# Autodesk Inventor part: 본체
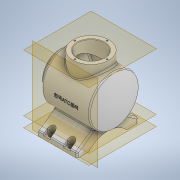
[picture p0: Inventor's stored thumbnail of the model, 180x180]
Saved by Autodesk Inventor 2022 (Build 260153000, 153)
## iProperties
Created: 2023-04
Part Number: 본체
Material: 일반
Document SubType Name: Modeling
Designer: Admin
Density: 1 g/cm^3
Appearance: 기본값
Author: Admin
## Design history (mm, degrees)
sketch "스케치1"
  geometry: L1 (-348.762, 0)-(521.266, 0) reference; L2 (0, -10.134)-(0, 60.805) reference; L3 (-224.472, 0)-(396.976, 0); L4 (-55.746, 0)-(-55.746, 36); L5 (-55.746, 36)-(-43.746, 36); L6 (-43.746, 36)-(-43.746, 50); L7 (-43.746, 50)-(52.59, 50); A1 r 113 centre (-48.746, 0) between (64.254, 0) and (52.59, 50); 1 further point
  constraints: 10 end point, 5 point on line, 3 perpendicular, 2 point on circle, 1 centre point, 1 vertical
  dimensions: "d3" = 72 diameter of L5 L3; "d4" = 50 distance between parallel lines of L1 L7; "d5" = 12 distance of L4.end L5.end; "d6" = 226 diameter of A1; "d7" = 48.74631 distance from line of L2 A1.centre; "d8" = 120 distance from line of A1.start L4
revolve "회전1" sketch "스케치1" stored, may be unused: angle "d9" = 360 deg
sketch "스케치2"
  geometry: L1 (-108.704, 0)-(76.451, 0) reference; L2 (0, -92.467)-(0, 110.746) reference; L3 (-34.165, -15.107)-(-67, -62); L4 (-67, -62)-(-77, -62); L5 (-77, -62)-(-77, 62); L6 (-77, 62)-(-67, 62); L7 (-67, 62)-(-34.165, 15.107); L8 (-34.165, 15.107)-(-34.165, -15.107); 1 further point
  constraints: 12 end point, 2 perpendicular, 1 horizontal, 1 parallel, 1 other
  dimensions: "d12" = 124 distance of L4.end L5.end; "d13" = 10 distance of L5.end L6.end; "d14" = 55 deg angle of L7 L6; "d15" = 55 deg angle of L3 L4; "d16" = 10 distance of L3.end L4.end; "d17" = 15.1066 distance from line of L1 L7.end; "d18" = 77 distance between parallel lines of L2 L5
extrude "돌출1" join sketch "스케치2" stored distance "d19" = 80; taper "d20" = 0 deg
node "작업 평면1"
sketch "스케치3"
  geometry: L1 (55.746, 36)-(55.746, -36) reference; L2 (79.746, 0)-(-88.254, 0) reference; L3 (0, -86.8)-(0, 86.8) reference; C1 r 36 at (-6.254, 0); C2 r 27 at (-6.254, 0); 1 further point
  constraints: 2 centre point, 1 coincident, 1 point on line
  dimensions: "d22" = 72 diameter of C1; "d23" = 62 distance from line of C1.centre L1; "d24" = 54 diameter of C2
extrude "돌출2" join sketch "스케치3" stored distance "d25" = 40; taper "d26" = 0 deg
sketch "스케치4"
  geometry: L1 (-92.77, 0)-(99.642, 0); L2 (0, -105.4)-(0, 93.4) reference; L3 (-55.746, -36)-(-55.746, 36) reference; L4 (-55.746, 27)-(-36.746, 27); L5 (-36.746, 27)-(-36.746, 40); L6 (57.254, 40.2)-(57.254, 39.154); L7 (64.254, 0)-(64.254, 54.671); L8 (-33.746, 43)-(46.723, 43); L9 (56.861, 40.2)-(57.254, 40.2); L10 (-55.746, 27)-(-55.746, 0); L11 (-116.841, 0)-(170.726, 0); A1 r 113 centre (-48.746, 0) between (52.59, -50) and (52.59, 50) reference; A2 r 113 centre (-55.746, 0) between (57.254, 0) and (49.518, 41.091); A3 r 3 centre (-33.746, 40) between (-33.746, 43) and (-36.746, 40); A4 r 3 centre (46.723, 40) between (49.518, 41.091) and (46.723, 43); 6 further points
  constraints: 18 end point, 10 point on circle, 6 tangent, 4 perpendicular, 3 centre point, 3 point on line, 2 horizontal, 1 equal radius, 1 vertical, 6 other
  dimensions: "d27" = 7 distance between parallel lines of L6 L7; "d28" = 226 diameter of A2; "d29" = 27 distance of the line from the sketch origin of L4; "d30" = 43 distance of the line from the sketch origin of L8; "d31" = 19 distance of L4.start L4.end; "d32" = 3 radius of A3
revolve "회전2" sketch "스케치4" stored, may be unused: angle "d33" = 360 deg
sketch "스케치5"
  geometry: L1 (-64.144, -60)-(74.974, -60); L2 (-62, -77)-(62, -77) reference; L3 (-91.968, 0)-(102.797, 0) reference; L4 (0, -210.029)-(0, 110.838) reference; A1 r 52.096 centre (0, -112.096) between (-38.5, -77) and (38.5, -77); 1 further point
  constraints: 3 point on line, 2 end point, 2 point on circle, 1 centre point, 1 horizontal, 1 tangent
  dimensions: "d34" = 17 distance between parallel lines of L2 L1; "d35" = 77 distance of A1.start A1.end
extrude "돌출3" cut sketch "스케치5" distance "d36" = 100; taper "d37" = 0 deg
sketch "스케치6"
  geometry: C1 r 36 at (-6.254, 0) reference; C2 r 27 at (-6.254, 0); 1 further point
  constraints: 1 centre point, 1 coincident
  dimensions: "d38" = 54 diameter of C2
extrude "돌출4" cut sketch "스케치6" distance "d39" = 40; taper "d40" = 0 deg
sketch "스케치7"
  geometry: L1 (-86, 0)-(82, 0) reference; L2 (-6.254, 86.8)-(-6.254, -86.8) reference; C1 r 27 at (0, 0) reference; A1 r 32.5 centre (0, 0) between (32.5, 0) and (0, 32.5); 3 further points
  constraints: 4 point on circle, 3 point on line, 1 centre point, 1 coincident
  dimensions: "d41" = 65 diameter of A1; "d42" = 32.5 distance from line of L1 point (0, -32.5); "d43" = 32.5 distance from line of L1 A1.end
hole "구멍1" sketch "스케치7" at (32.5, 0), (0, 32.5), (-32.5, 0), (0, -32.5) diameter "d44" = 3.242; stored, may be unused: countersink angle "d48" = 90 deg, drill point angle "d50" = 118 deg; dims "d45" = 8, "d46" = 4, "d47" = 2, "d49" = 10
sketch "스케치8"
  geometry: L1 (0, -105.4)-(0, 93.4) reference; L2 (-86.8, 0)-(86.8, 0) reference; A1 r 32.5 centre (0, 0) between (0, 32.5) and (-32.5, 0); 3 further points
  constraints: 4 point on circle, 4 point on line, 1 centre point, 1 coincident
  dimensions: "d51" = 65 diameter of A1
hole "구멍2" sketch "스케치8" at (0, 32.5), (-32.5, 0), (0, -32.5), (32.5, 0) diameter "d52" = 3.242; stored, may be unused: countersink angle "d56" = 90 deg, drill point angle "d58" = 118 deg; dims "d53" = 8, "d54" = 4, "d55" = 2, "d57" = 10
node "작업 평면2"
sketch "스케치9"
  geometry: L1 (-55.746, -36)-(-55.746, 36) reference; L2 (-79.746, 0)-(88.254, 0) reference; 2 further points
  constraints: 1 point on line, 1 other
  dimensions: "d60" = 62 distance from line of L1 point (6.254, 0)
feature "엠보싱1" sketch "스케치9" dims "d3" = 72, "d4" = 50, "d5" = 12, "d6" = 226, "d7" = 48.74631, "d8" = 120, "d61" = 0.5, "d62" = 0
node "작업 평면3"
sketch "스케치11"
  geometry: L1 (0, 124)-(80, 124) reference; L2 (0, 0)-(80, 0) reference; L3 (0, 100.5)-(0, 124) reference; L4 (0, 0)-(0, 23.5) reference; 5 further points
  dimensions: "d72" = 8 distance from line of L1 point (20, 116); "d73" = 8 distance from line of L1 point (60, 116); "d74" = 8 distance from line of L2 point (20, 8); "d75" = 8 distance from line of L2 point (60, 8); "d76" = 40 distance of point (60, 116) point (20, 116); "d77" = 40 distance of point (60, 8) point (20, 8); "d78" = 20 distance from line of L3 point (20, 116); "d79" = 20 distance from line of L4 point (20, 8)
hole "구멍3" sketch "스케치11" at (20, 116), (60, 116), (20, 8), (60, 8) diameter "d80" = 9; stored, may be unused: countersink angle "d84" = 90 deg, drill point angle "d86" = 0 deg; dims "d81" = 8, "d82" = 4, "d83" = 2, "d85" = 6
node "작업 평면4"
sketch "스케치12"
  geometry: L1 (-27, 54)-(-27, 62); L2 (40, 62)-(-40, 62) reference; L3 (-13, 54)-(-13, 62); L4 (-13, 62)-(-27, 62); L5 (13, 54)-(13, 62); L6 (13, 62)-(27, 62); L7 (27, 62)-(27, 54); L8 (-27, -54)-(-27, -62); L9 (40, -62)-(-40, -62) reference; L10 (-13, -54)-(-13, -62); L11 (-13, -62)-(-27, -62); L12 (13, -54)-(13, -62); L13 (27, -62)-(27, -54); L14 (27, -62)-(13, -62); C1 r 4.5 at (-20, 54) reference; C2 r 4.5 at (20, 54) reference; C3 r 4.5 at (-20, -54) reference; C4 r 4.5 at (20, -54) reference; A1 r 7 centre (-20, 54) between (-27, 54) and (-13, 54); A2 r 7 centre (20, 54) between (13, 54) and (27, 54); A3 r 7 centre (-20, -54) between (-27, -54) and (-13, -54); A4 r 7 centre (20, -54) between (13, -54) and (27, -54); 7 further points
  constraints: 24 end point, 14 point on line, 8 point on circle, 4 centre point, 4 coincident, 4 perpendicular, 4 tangent, 2 vertical
  dimensions: "d88" = 14 diameter of A1; "d89" = 14 diameter of A2; "d90" = 14 diameter of A3; "d91" = 14 diameter of A4
extrude "돌출5" cut sketch "스케치12" distance "d92" = 21; taper "d93" = 0 deg
chamfer "모따기1" distance "d94" = 1; stored, may be unused: second distance "d95" = 2, angle "d96" = 45 deg
fillet "모깎기1" dims "d97" = 3
chamfer "모따기2" distance "d98" = 1; stored, may be unused: second distance "d99" = 2, angle "d100" = 45 deg
node "솔리드1"
feature "A9D066F2-1C7D-4E18-AEED-F7BC21143FA4" dims "d80" = 9, "d81" = 8, "d82" = 4, "d83" = 2, "d84" = 90 deg, "d85" = 6, "d86" = 0
other parameters: "d21" = 65, "d87" = -71
